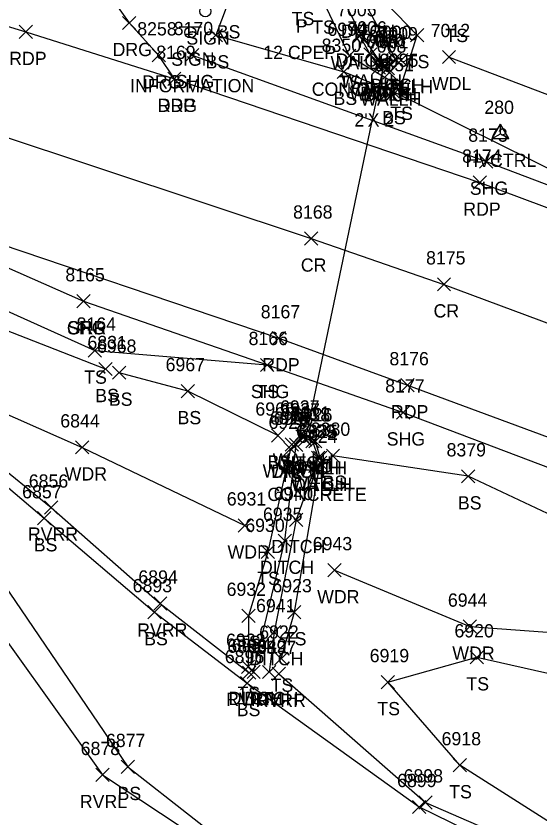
# Model space of a CAD drawing. Extents: x 1588028 to 1589597, y 137576 to 138176.
# Drawn here: x 1589126.2 to 1589205.2, y 137712.9 to 137833.8 of the extents above; entities that cross this region are included whole.
import ezdxf

# ---------------------------------------------------------------- set-up
doc = ezdxf.new("R2010")
doc.units = 0
for name, color, linetype in [('C_A', 7, 'Continuous'), ('C_I', 7, 'Continuous'), ('CPSM', 7, 'Continuous'), ('D_A', 7, 'Continuous'), ('D_C', 7, 'Continuous'), ('D_I', 7, 'Continuous'), ('D_TIC', 7, 'Continuous'), ('DD', 7, 'Continuous'), ('DDEFAULT', 7, 'Continuous'), ('DHW', 7, 'Continuous'), ('L_A', 7, 'Continuous'), ('L_I', 7, 'Continuous'), ('L_TIC', 7, 'Continuous'), ('LAWA', 7, 'Continuous'), ('LAWE', 7, 'Continuous'), ('LELB', 7, 'Continuous'), ('P_A', 7, 'Continuous'), ('P_I', 7, 'Continuous'), ('P_TIC', 7, 'Continuous'), ('PET', 7, 'Continuous'), ('PRC', 7, 'Continuous'), ('PSU', 7, 'Continuous'), ('R_A', 7, 'Continuous'), ('R_I', 7, 'Continuous'), ('R_TIC', 7, 'Continuous'), ('RDG', 7, 'Continuous'), ('RGR', 7, 'Continuous'), ('S_A', 7, 'Continuous'), ('S_C', 7, 'Continuous'), ('SSGN', 7, 'Continuous')]:
    doc.layers.add(name, color=color, linetype=linetype)

msp = doc.modelspace()

# ---------------------------------------------------------------- linework, layer by layer
at = {"layer": 'CPSM'}
for p, q in [((1589198.01, 137815.36), (1589199.26, 137817.52)), ((1589200.51, 137815.36), (1589199.26, 137817.52)), ((1589199.26, 137816.08), (1589199.26, 137817.52)), ((1589198.01, 137815.36), (1589199.26, 137816.08)), ((1589199.26, 137816.08), (1589199.26, 137816.08)), ((1589199.26, 137816.08), (1589200.51, 137815.36)), ((1589198.01, 137815.36), (1589200.51, 137815.36))]:
    msp.add_line(p, q, dxfattribs=at)
at = {"layer": 'D_TIC'}
for points in [[(1589177.02, 137829.81), (1589179.02, 137831.81)], [(1589179.02, 137829.81), (1589177.02, 137831.81)], [(1589177.15, 137830.2), (1589179.15, 137832.2)], [(1589179.15, 137830.2), (1589177.15, 137832.2)], [(1589178.61, 137827.05), (1589180.61, 137829.05)], [(1589180.61, 137827.05), (1589178.61, 137829.05)], [(1589182.37, 137826.39), (1589184.37, 137828.39)], [(1589184.37, 137826.39), (1589182.37, 137828.39)], [(1589183.27, 137826.17), (1589185.27, 137828.17)], [(1589185.27, 137826.17), (1589183.27, 137828.17)], [(1589179.88, 137825.08), (1589181.88, 137827.08)], [(1589181.88, 137825.08), (1589179.88, 137827.08)], [(1589180.26, 137825.74), (1589182.26, 137827.74)], [(1589182.26, 137825.74), (1589180.26, 137827.74)], [(1589180.57, 137825.18), (1589182.57, 137827.18)], [(1589182.57, 137825.18), (1589180.57, 137827.18)], [(1589181.25, 137824.97), (1589183.25, 137826.97)], [(1589183.25, 137824.97), (1589181.25, 137826.97)], [(1589181.5, 137824.32), (1589183.5, 137826.32)], [(1589183.5, 137824.32), (1589181.5, 137826.32)], [(1589168.3, 137769.89), (1589170.3, 137771.89)], [(1589170.3, 137769.89), (1589168.3, 137771.89)], [(1589168.38, 137769.46), (1589170.38, 137771.46)], [(1589170.38, 137769.46), (1589168.38, 137771.46)], [(1589166.78, 137768.23), (1589168.78, 137770.23)], [(1589168.78, 137768.23), (1589166.78, 137770.23)], [(1589167.42, 137768.19), (1589169.42, 137770.19)], [(1589169.42, 137768.19), (1589167.42, 137770.19)], [(1589168.78, 137768.97), (1589170.78, 137770.97)], [(1589170.78, 137768.97), (1589168.78, 137770.97)], [(1589169.9, 137768.71), (1589171.9, 137770.71)], [(1589171.9, 137768.71), (1589169.9, 137770.71)], [(1589170.32, 137768.71), (1589172.32, 137770.71)], [(1589172.32, 137768.71), (1589170.32, 137770.71)], [(1589170.74, 137766.24), (1589172.74, 137768.24)], [(1589172.74, 137766.24), (1589170.74, 137768.24)], [(1589171.05, 137766.21), (1589173.05, 137768.21)], [(1589173.05, 137766.21), (1589171.05, 137768.21)], [(1589167.42, 137756.85), (1589169.42, 137758.85)], [(1589169.42, 137756.85), (1589167.42, 137758.85)], [(1589165.72, 137753.72), (1589167.72, 137755.72)], [(1589167.72, 137753.72), (1589165.72, 137755.72)], [(1589164.11, 137739.94), (1589166.11, 137741.94)], [(1589166.11, 137739.94), (1589164.11, 137741.94)], [(1589161.01, 137733.95), (1589163.01, 137735.95)], [(1589163.01, 137733.95), (1589161.01, 137735.95)], [(1589163.35, 137733.92), (1589165.35, 137735.92)], [(1589165.35, 137733.92), (1589163.35, 137735.92)]]:
    msp.add_lwpolyline(points, dxfattribs=at)
at = {"layer": 'DD'}
for points in [[(1589174.09, 137841.27), (1589178.94, 137835.55), (1589183.37, 137827.39), (1589182.25, 137825.97), (1589181.26, 137826.74), (1589178.15, 137831.2), (1589174.19, 137838.92)], [(1589162.01, 137734.95), (1589166.72, 137754.72), (1589168.42, 137769.19), (1589169.38, 137770.46), (1589170.9, 137769.71), (1589171.74, 137767.24), (1589168.42, 137757.85), (1589165.11, 137740.94), (1589164.35, 137734.92)]]:
    msp.add_lwpolyline(points, dxfattribs=at)
at = {"layer": 'DDEFAULT'}
msp.add_lwpolyline([(1589181.57, 137826.18), (1589169.78, 137769.97)], dxfattribs=at)
at = {"layer": 'DHW'}
for points in [[(1589178.02, 137830.81), (1589179.61, 137828.05), (1589180.88, 137826.08), (1589182.5, 137825.32), (1589184.27, 137827.17)], [(1589172.05, 137767.21), (1589171.32, 137769.71), (1589169.3, 137770.89), (1589167.78, 137769.23)]]:
    msp.add_lwpolyline(points, dxfattribs=at)
at = {"layer": 'L_TIC'}
for points in [[(1589155.32, 137829.93), (1589157.32, 137831.93)], [(1589157.32, 137829.93), (1589155.32, 137831.93)], [(1589185.69, 137829.97), (1589187.69, 137831.97)], [(1589187.69, 137829.97), (1589185.69, 137831.97)], [(1589175.44, 137826.84), (1589177.44, 137828.84)], [(1589177.44, 137826.84), (1589175.44, 137828.84)], [(1589190.48, 137826.66), (1589192.48, 137828.66)], [(1589192.48, 137826.66), (1589190.48, 137828.66)], [(1589174.62, 137824.43), (1589176.62, 137826.43)], [(1589176.62, 137824.43), (1589174.62, 137826.43)], [(1589181.94, 137821.51), (1589183.94, 137823.51)], [(1589183.94, 137821.51), (1589181.94, 137823.51)], [(1589183.21, 137822.17), (1589185.21, 137824.17)], [(1589185.21, 137822.17), (1589183.21, 137824.17)], [(1589137.04, 137782.39), (1589139.04, 137784.39)], [(1589139.04, 137782.39), (1589137.04, 137784.39)], [(1589163.04, 137780.22), (1589165.04, 137782.22)], [(1589165.04, 137780.22), (1589163.04, 137782.22)], [(1589138.68, 137779.61), (1589140.68, 137781.61)], [(1589140.68, 137779.61), (1589138.68, 137781.61)], [(1589140.73, 137779.06), (1589142.73, 137781.06)], [(1589142.73, 137779.06), (1589140.73, 137781.06)], [(1589151.09, 137776.28), (1589153.09, 137778.28)], [(1589153.09, 137776.28), (1589151.09, 137778.28)], [(1589164.68, 137769.58), (1589166.68, 137771.58)], [(1589166.68, 137769.58), (1589164.68, 137771.58)], [(1589135.15, 137767.8), (1589137.15, 137769.8)], [(1589137.15, 137767.8), (1589135.15, 137769.8)], [(1589166.56, 137767.59), (1589168.56, 137769.59)], [(1589168.56, 137767.59), (1589166.56, 137769.59)], [(1589171.03, 137765.48), (1589173.03, 137767.48)], [(1589173.03, 137765.48), (1589171.03, 137767.48)], [(1589172.98, 137766.54), (1589174.98, 137768.54)], [(1589174.98, 137766.54), (1589172.98, 137768.54)], [(1589193.38, 137763.43), (1589195.38, 137765.43)], [(1589195.38, 137763.43), (1589193.38, 137765.43)], [(1589130.45, 137758.72), (1589132.45, 137760.72)], [(1589132.45, 137758.72), (1589130.45, 137760.72)], [(1589129.4, 137757.11), (1589131.4, 137759.11)], [(1589131.4, 137757.11), (1589129.4, 137759.11)], [(1589159.7, 137756.03), (1589161.7, 137758.03)], [(1589161.7, 137756.03), (1589159.7, 137758.03)], [(1589163.14, 137752.05), (1589165.14, 137754.05)], [(1589165.14, 137752.05), (1589163.14, 137754.05)], [(1589173.22, 137749.28), (1589175.22, 137751.28)], [(1589175.22, 137749.28), (1589173.22, 137751.28)], [(1589146.93, 137744.25), (1589148.93, 137746.25)], [(1589148.93, 137744.25), (1589146.93, 137746.25)], [(1589146.06, 137742.95), (1589148.06, 137744.95)], [(1589148.06, 137742.95), (1589146.06, 137744.95)], [(1589167.15, 137742.94), (1589169.15, 137744.94)], [(1589169.15, 137742.94), (1589167.15, 137744.94)], [(1589160.24, 137742.4), (1589162.24, 137744.4)], [(1589162.24, 137742.4), (1589160.24, 137744.4)], [(1589193.61, 137740.77), (1589195.61, 137742.77)], [(1589195.61, 137740.77), (1589193.61, 137742.77)], [(1589165.16, 137735.94), (1589167.16, 137737.94)], [(1589167.16, 137735.94), (1589165.16, 137737.94)], [(1589194.69, 137736.14), (1589196.69, 137738.14)], [(1589196.69, 137736.14), (1589194.69, 137738.14)], [(1589160.16, 137734.71), (1589162.16, 137736.71)], [(1589162.16, 137734.71), (1589160.16, 137736.71)], [(1589160.35, 137733.82), (1589162.35, 137735.82)], [(1589162.35, 137733.82), (1589160.35, 137735.82)], [(1589164.8, 137733.64), (1589166.8, 137735.64)], [(1589166.8, 137733.64), (1589164.8, 137735.64)], [(1589160.02, 137732.26), (1589162.02, 137734.26)], [(1589162.02, 137732.26), (1589160.02, 137734.26)], [(1589181.26, 137732.4), (1589183.26, 137734.4)], [(1589183.26, 137732.4), (1589181.26, 137734.4)], [(1589142.04, 137719.61), (1589144.04, 137721.61)], [(1589144.04, 137719.61), (1589142.04, 137721.61)], [(1589192.1, 137719.87), (1589194.1, 137721.87)], [(1589194.1, 137719.87), (1589192.1, 137721.87)], [(1589138.23, 137718.4), (1589140.23, 137720.4)], [(1589140.23, 137718.4), (1589138.23, 137720.4)], [(1589185.97, 137713.57), (1589187.97, 137715.57)], [(1589187.97, 137713.57), (1589185.97, 137715.57)], [(1589186.94, 137714.26), (1589188.94, 137716.26)], [(1589188.94, 137714.26), (1589186.94, 137716.26)]]:
    msp.add_lwpolyline(points, dxfattribs=at)
at = {"layer": 'LAWA'}
for points in [[(1589191.48, 137827.66), (1589208.47, 137821.19), (1589231.01, 137810.22), (1589260.79, 137799.99), (1589288.54, 137790.36), (1589312.49, 137778.55), (1589337.68, 137767.31), (1589356.85, 137760.89), (1589388.23, 137746.7), (1589420.91, 137733.88), (1589453.12, 137717.84), (1589474.94, 137709.38)], [(1588990.27, 137820.39), (1589015.31, 137815.18), (1589044.24, 137809.21), (1589082.76, 137797.73), (1589102.27, 137783.77), (1589136.15, 137768.8), (1589160.7, 137757.03)], [(1589174.22, 137750.28), (1589194.61, 137741.77), (1589225.59, 137739.5), (1589259.02, 137733.29), (1589293.77, 137713.14), (1589318.53, 137702.11), (1589332.78, 137696.04)]]:
    msp.add_lwpolyline(points, dxfattribs=at)
at = {"layer": 'LAWE'}
for points in [[(1588965.44, 137832.87), (1588973.43, 137818.62), (1588989.6, 137813.18), (1589022.84, 137804.12), (1589064.64, 137785.89), (1589085.42, 137779.69), (1589097.72, 137781.17), (1589112.63, 137775.03), (1589131.45, 137759.72), (1589147.93, 137745.25), (1589161.35, 137734.82)], [(1588998.37, 137781.01), (1589022.99, 137780.11), (1589053.11, 137769.29), (1589085.17, 137761.52), (1589118.32, 137748.59), (1589139.23, 137719.4), (1589162.49, 137704.02), (1589194.14, 137678.84), (1589218.55, 137662.87), (1589237.06, 137655.88), (1589274.24, 137640.2), (1589299.98, 137630.61), (1589325.3, 137627.35), (1589364.55, 137614.89), (1589400.15, 137603.63), (1589430.64, 137600.05), (1589464.28, 137596.09), (1589486.71, 137581.4)], [(1589165.8, 137734.64), (1589187.94, 137715.26), (1589212.73, 137704.5), (1589228.51, 137693.02), (1589244.33, 137677.06), (1589269.62, 137665.25), (1589295.65, 137657.92), (1589324.97, 137652.81), (1589365.32, 137641.86), (1589399.41, 137634.7), (1589423.88, 137632.18), (1589457.23, 137620.82), (1589479.74, 137612.88)]]:
    msp.add_lwpolyline(points, dxfattribs=at)
at = {"layer": 'LELB'}
for points in [[(1589172.43, 137836.17), (1589176.44, 137827.84), (1589184.21, 137823.17), (1589186.69, 137830.97), (1589175.8, 137842.19)], [(1589158, 137835.46), (1589156.32, 137830.93), (1589175.62, 137825.43), (1589182.94, 137822.51), (1589209.46, 137809.41), (1589234.23, 137800.33), (1589267.46, 137786.74), (1589294.29, 137776.74), (1589322.35, 137767.05), (1589346.37, 137758.08), (1589352.86, 137754.06), (1589353.51, 137751.68), (1589354.61, 137751.57), (1589355.75, 137752.57)], [(1588982.15, 137832.74), (1589014.45, 137822.9), (1589047.33, 137817.07), (1589086.55, 137806.43), (1589114.04, 137794.2), (1589138.04, 137783.39), (1589164.04, 137781.22)], [(1588992.37, 137810.47), (1589023.33, 137801.66), (1589065.26, 137783.21), (1589085.4, 137777.87), (1589097.27, 137780.08), (1589112.23, 137773.55), (1589130.4, 137758.11), (1589147.06, 137743.95), (1589161.02, 137733.26), (1589186.97, 137714.57), (1589213.06, 137701.82), (1589227.47, 137691.94), (1589245.18, 137673.31), (1589268.48, 137660.8), (1589296.93, 137655.07), (1589325.66, 137650.73)], [(1589139.68, 137780.61), (1589111.56, 137791.56), (1589090.72, 137796.64)], [(1588992.54, 137792.39), (1589023.3, 137782.03), (1589052.1, 137771.44), (1589084.42, 137763.28), (1589121.54, 137752.14), (1589143.04, 137720.61), (1589163.05, 137704.95), (1589194.58, 137680.14), (1589220, 137665.12), (1589237.76, 137657.31), (1589273.63, 137642.37), (1589300.04, 137631.76), (1589324.52, 137628.67), (1589366.23, 137617.74), (1589400.05, 137606.05), (1589430.12, 137603.56), (1589464.26, 137598.64), (1589483.45, 137589.04)], [(1589165.68, 137770.58), (1589152.09, 137777.28), (1589141.73, 137780.06)], [(1589167.56, 137768.59), (1589164.14, 137753.05), (1589161.24, 137743.4), (1589161.16, 137735.71)], [(1589346.98, 137708.09), (1589339.5, 137707.7), (1589337.39, 137703.26), (1589330.57, 137699.32), (1589318.71, 137707.48), (1589314.78, 137719.03), (1589294.5, 137728.6), (1589257.75, 137742.55), (1589219.17, 137752.77), (1589194.38, 137764.43), (1589173.98, 137767.54)], [(1589166.16, 137736.94), (1589168.15, 137743.94), (1589172.03, 137766.48)], [(1589211.6, 137709.12), (1589193.1, 137720.87), (1589182.26, 137733.4), (1589195.69, 137737.14), (1589211.53, 137733.59)]]:
    msp.add_lwpolyline(points, dxfattribs=at)
at = {"layer": 'P_TIC'}
for points in [[(1589126.64, 137830.45), (1589128.64, 137832.45)], [(1589128.64, 137830.45), (1589126.64, 137832.45)], [(1589151.74, 137826.96), (1589153.74, 137828.96)], [(1589153.74, 137826.96), (1589151.74, 137828.96)], [(1589149.05, 137823.37), (1589151.05, 137825.37)], [(1589151.05, 137823.37), (1589149.05, 137825.37)], [(1589196.07, 137810.88), (1589198.07, 137812.88)], [(1589198.07, 137810.88), (1589196.07, 137812.88)], [(1589195.14, 137807.72), (1589197.14, 137809.72)], [(1589197.14, 137807.72), (1589195.14, 137809.72)], [(1589169.7, 137799.29), (1589171.7, 137801.29)], [(1589171.7, 137799.29), (1589169.7, 137801.29)], [(1589189.72, 137792.38), (1589191.72, 137794.38)], [(1589191.72, 137792.38), (1589189.72, 137794.38)], [(1589135.35, 137789.83), (1589137.35, 137791.83)], [(1589137.35, 137789.83), (1589135.35, 137791.83)], [(1589164.82, 137784.25), (1589166.82, 137786.25)], [(1589166.82, 137784.25), (1589164.82, 137786.25)], [(1589163.04, 137780.22), (1589165.04, 137782.22)], [(1589165.04, 137780.22), (1589163.04, 137782.22)], [(1589184.23, 137777.17), (1589186.23, 137779.17)], [(1589186.23, 137777.17), (1589184.23, 137779.17)], [(1589183.55, 137773.07), (1589185.55, 137775.07)], [(1589185.55, 137773.07), (1589183.55, 137775.07)]]:
    msp.add_lwpolyline(points, dxfattribs=at)
at = {"layer": 'PET'}
for points in [[(1588976.42, 137837.98), (1588964.71, 137855.4), (1588953.74, 137871.46), (1588980.82, 137866.91), (1589021.21, 137859.55), (1589054.58, 137852.92), (1589087.36, 137843.77), (1589127.64, 137831.45), (1589150.05, 137824.37), (1589196.14, 137808.72), (1589243.87, 137790.96), (1589276.87, 137778.08), (1589322.25, 137759.62), (1589367.82, 137740.82), (1589401.87, 137726.11), (1589432.81, 137712.85), (1589459.76, 137701.46)], [(1588976.42, 137837.98), (1589015.38, 137829.77), (1589047.77, 137821.87), (1589087.62, 137811.07), (1589117.34, 137801.67), (1589165.82, 137785.25), (1589185.23, 137778.17), (1589232.28, 137760.8), (1589265.32, 137747.81), (1589310.31, 137729.83), (1589359.63, 137709.23), (1589389.55, 137696.8), (1589422.31, 137682.69), (1589446.91, 137672.54)]]:
    msp.add_lwpolyline(points, dxfattribs=at)
at = {"layer": 'PRC'}
msp.add_lwpolyline([(1588964.71, 137855.4), (1588980.14, 137852.51), (1589018.19, 137844.35), (1589051.57, 137836.27), (1589092.27, 137825.07), (1589122.68, 137816.23), (1589170.7, 137800.29), (1589190.72, 137793.38), (1589238.44, 137775.62), (1589271.31, 137762.4), (1589315.94, 137744.35), (1589366.22, 137723.58), (1589395.71, 137710.87), (1589428.18, 137697.42), (1589453.33, 137686.42)], dxfattribs=at)
at = {"layer": 'PSU'}
for points in [[(1589152.74, 137827.96), (1589197.07, 137811.88), (1589244.81, 137793.79), (1589277.33, 137781.11), (1589323.36, 137762.65), (1589353.23, 137749.52), (1589368.68, 137743.62), (1589402.84, 137728.77), (1589433.2, 137714.7), (1589460.72, 137703.44)], [(1589136.35, 137790.83), (1589164.04, 137781.22), (1589184.55, 137774.07), (1589230.78, 137756.58), (1589263.84, 137744.47), (1589309.17, 137726.92), (1589358.43, 137707.04), (1589387.87, 137693.92), (1589420.52, 137679.79), (1589445.83, 137669.38)]]:
    msp.add_lwpolyline(points, dxfattribs=at)
at = {"layer": 'R_TIC'}
for points in [[(1589142.24, 137831.79), (1589144.24, 137833.79)], [(1589144.24, 137831.79), (1589142.24, 137833.79)], [(1589146.71, 137826.91), (1589148.71, 137828.91)], [(1589148.71, 137826.91), (1589146.71, 137828.91)], [(1589146.71, 137826.91), (1589148.71, 137828.91)], [(1589148.71, 137826.91), (1589146.71, 137828.91)], [(1589149.05, 137823.37), (1589151.05, 137825.37)], [(1589151.05, 137823.37), (1589149.05, 137825.37)], [(1589135.35, 137789.83), (1589137.35, 137791.83)], [(1589137.35, 137789.83), (1589135.35, 137791.83)]]:
    msp.add_lwpolyline(points, dxfattribs=at)
at = {"layer": 'RDG'}
for points in [[(1589030.3, 137954.92), (1589069.21, 137915.71), (1589093.48, 137893.77), (1589119.98, 137869.52), (1589132.81, 137847.36), (1589143.24, 137832.79), (1589147.71, 137827.91)], [(1589150.05, 137824.37), (1589147.71, 137827.91)]]:
    msp.add_lwpolyline(points, dxfattribs=at)
at = {"layer": 'RGR'}
msp.add_lwpolyline([(1588981.28, 137836.13), (1589015.23, 137828.95), (1589047.72, 137821.35), (1589087.45, 137810.42), (1589116.48, 137799.61), (1589136.35, 137790.83)], dxfattribs=at)
at = {"layer": 'SSGN'}
for p, q in [((1589150.8, 137832.19), (1589154.13, 137832.19)), ((1589152.45, 137831.36), (1589152.45, 137831.36))]:
    msp.add_line(p, q, dxfattribs=at)
for centre in [(1589154.73, 137834.55), (1589152.45, 137831.36)]:
    msp.add_circle(centre, 0.833, dxfattribs=at)

# ---------------------------------------------------------------- texts
at = {"layer": 'C_A'}
msp.add_text('HVCTRL', height=2, dxfattribs=at).set_placement((1589193.96, 137811.08))
at = {"layer": 'C_I'}
msp.add_text('280', height=2, dxfattribs=at).set_placement((1589196.81, 137819.08))
at = {"layer": 'D_A'}
for s, p in [('P', (1589168.37, 137831.35)), ('DITCH', (1589175.17, 137830.55)), ('DITCH', (1589174.39, 137826.2)), ('WALLH', (1589173.61, 137825.81)), ('WALLH', (1589175.2, 137823.05)), ('DITCH', (1589179.6, 137822.39)), ('DITCH', (1589177.5, 137821.74)), ('BOXC', (1589178.07, 137821.18)), ('WALLH', (1589179.86, 137822.17)), ('WALLH', (1589176.47, 137821.08)), ('WALLH', (1589178.09, 137820.32)), ('DITCH', (1589178.48, 137820.97)), ('WALLH', (1589164.89, 137765.89)), ('DITCH', (1589165.61, 137765.46)), ('BOXC', (1589166.28, 137764.97)), ('WALLH', (1589166.91, 137764.71)), ('DITCH', (1589167.14, 137764.71)), ('WALLH', (1589163.37, 137764.23)), ('DITCH', (1589164.66, 137764.19)), ('WALLH', (1589167.64, 137762.21)), ('DITCH', (1589167.97, 137762.24)), ('DITCH', (1589164.66, 137752.85)), ('DITCH', (1589162.96, 137749.72)), ('DITCH', (1589161.35, 137735.94)), ('DITCH', (1589158.24, 137729.95)), ('DITCH', (1589160.59, 137729.92))]:
    msp.add_text(s, height=2, dxfattribs=at).set_placement(p)
at = {"layer": 'D_C'}
for s, p in [('12 CPEP', (1589163.46, 137827.35)), ('CONCRETE', (1589170.77, 137821.81)), ("2'X 2'", (1589177.21, 137817.18)), ('CONCRETE', (1589164.07, 137760.71))]:
    msp.add_text(s, height=2, dxfattribs=at).set_placement(p)
at = {"layer": 'D_I'}
for s, p in [('7005', (1589174.6, 137833.81)), ('7006', (1589176.14, 137831.05)), ('7002', (1589177.85, 137829.74)), ('7000', (1589179.86, 137830.39)), ('7009', (1589180.84, 137830.17)), ('7007', (1589177.47, 137829.08)), ('7010', (1589178.71, 137829.18)), ('7001', (1589179.4, 137828.97)), ('7008', (1589179.09, 137828.32)), ('6927', (1589165.99, 137773.89)), ('6937', (1589166.07, 137773.46)), ('7011', (1589167.58, 137772.97)), ('6938', (1589167.6, 137772.71)), ('6926', (1589167.95, 137772.71)), ('6928', (1589164.47, 137772.23)), ('6936', (1589165.06, 137772.19)), ('6939', (1589168.42, 137770.24)), ('6925', (1589168.75, 137770.21)), ('6940', (1589165.03, 137760.85)), ('6935', (1589163.42, 137757.72)), ('6941', (1589162.37, 137743.94)), ('6934', (1589158.7, 137737.95)), ('6942', (1589161.05, 137737.92))]:
    msp.add_text(s, height=2, dxfattribs=at).set_placement(p)
at = {"layer": 'L_A'}
for s, p in [('TS', (1589167.75, 137832.46)), ('TS', (1589170.84, 137831.17)), ('BS', (1589156.44, 137830.46)), ('TS', (1589190.94, 137829.91)), ('BS', (1589154.76, 137825.93)), ('TS', (1589185.1, 137825.97)), ('TS', (1589174.85, 137822.84)), ('WDL', (1589188.9, 137822.66)), ('BS', (1589174.06, 137820.43)), ('BS', (1589181.39, 137817.51)), ('TS', (1589182.62, 137818.17)), ('TS', (1589136.45, 137778.39)), ('BS', (1589138.12, 137775.61)), ('TS', (1589162.45, 137776.22)), ('BS', (1589140.17, 137775.06)), ('BS', (1589150.53, 137772.28)), ('BS', (1589164.12, 137765.58)), ('WDR', (1589133.51, 137763.8)), ('TS', (1589165.97, 137763.59)), ('BS', (1589172.42, 137762.54)), ('TS', (1589170.44, 137761.48)), ('BS', (1589192.82, 137759.43)), ('RVRR', (1589127.96, 137754.72)), ('BS', (1589128.84, 137753.11)), ('WDR', (1589158.07, 137752.03)), ('TS', (1589162.55, 137748.05)), ('WDR', (1589171.59, 137745.28)), ('RVRR', (1589144.44, 137740.25)), ('BS', (1589145.5, 137738.95)), ('TS', (1589166.56, 137738.94)), ('TS', (1589159.65, 137738.4)), ('WDR', (1589191.98, 137736.77)), ('TS', (1589164.57, 137731.94)), ('TS', (1589194.1, 137732.14)), ('TS', (1589159.57, 137730.71)), ('RVRR', (1589157.86, 137729.82)), ('RVRR', (1589162.31, 137729.64)), ('BS', (1589159.46, 137728.26)), ('TS', (1589180.67, 137728.4)), ('TS', (1589191.51, 137715.87)), ('BS', (1589141.48, 137715.61)), ('RVRL', (1589135.79, 137714.4))]:
    msp.add_text(s, height=2, dxfattribs=at).set_placement(p)
at = {"layer": 'L_I'}
for s, p in [('6994', (1589173.14, 137830.84)), ('7012', (1589188.71, 137830.66)), ('8350', (1589172.27, 137828.43)), ('6995', (1589180.91, 137826.17)), ('8351', (1589180.25, 137825.51)), ('8164', (1589135.3, 137786.39)), ('6831', (1589136.94, 137783.61)), ('8166', (1589161.25, 137784.22)), ('6968', (1589138.38, 137783.06)), ('6967', (1589148.73, 137780.28)), ('6966', (1589162.27, 137773.58)), ('6844', (1589132.84, 137771.8)), ('6929', (1589164.25, 137771.59)), ('8380', (1589170.63, 137770.54)), ('6924', (1589168.72, 137769.48)), ('8379', (1589191.11, 137767.43)), ('6856', (1589128.09, 137762.72)), ('6857', (1589127.09, 137761.11)), ('6931', (1589157.96, 137760.03)), ('6930', (1589160.75, 137756.05)), ('6943', (1589170.92, 137753.28)), ('6894', (1589144.62, 137748.25)), ('6893', (1589143.76, 137746.95)), ('6932', (1589157.93, 137746.4)), ('6923', (1589164.84, 137746.94)), ('6944', (1589191.31, 137744.77)), ('6920', (1589192.3, 137740.14)), ('6922', (1589162.85, 137739.94)), ('6933', (1589157.85, 137738.71)), ('6895', (1589158.04, 137737.82)), ('6897', (1589162.49, 137737.64)), ('6896', (1589157.66, 137736.26)), ('6919', (1589179.52, 137736.4)), ('6877', (1589139.73, 137723.61)), ('6918', (1589190.36, 137723.87)), ('6878', (1589135.92, 137722.4)), ('6899', (1589183.65, 137717.57)), ('6898', (1589184.63, 137718.26))]:
    msp.add_text(s, height=2, dxfattribs=at).set_placement(p)
at = {"layer": 'P_A'}
for s, p in [('RDP', (1589125.13, 137826.45)), ('SHG', (1589150.27, 137822.96)), ('RDP', (1589147.54, 137819.37)), ('SHG', (1589194.61, 137806.88)), ('RDP', (1589193.63, 137803.72)), ('CR', (1589169.13, 137795.29)), ('CR', (1589189.15, 137788.38)), ('SHG', (1589133.89, 137785.83)), ('RDP', (1589163.31, 137780.25)), ('SHG', (1589161.58, 137776.22)), ('RDP', (1589182.72, 137773.17)), ('SHG', (1589182.08, 137769.07))]:
    msp.add_text(s, height=2, dxfattribs=at).set_placement(p)
at = {"layer": 'P_I'}
for s, p in [('8170', (1589149.96, 137830.96)), ('8169', (1589147.31, 137827.37)), ('8173', (1589194.38, 137814.88)), ('8174', (1589193.45, 137811.72)), ('8168', (1589167.96, 137803.29)), ('8175', (1589188.02, 137796.38)), ('8165', (1589133.61, 137793.83)), ('8167', (1589163.08, 137788.25)), ('8166', (1589161.25, 137784.22)), ('8176', (1589182.49, 137781.17)), ('8177', (1589181.85, 137777.07))]:
    msp.add_text(s, height=2, dxfattribs=at).set_placement(p)
at = {"layer": 'R_A'}
for s, p in [('DRG', (1589140.73, 137827.79)), ('DRG', (1589145.2, 137822.91)), ('DRG', (1589145.2, 137822.91)), ('DRG', (1589147.54, 137819.37)), ('GRR', (1589133.84, 137785.83))]:
    msp.add_text(s, height=2, dxfattribs=at).set_placement(p)
at = {"layer": 'R_I'}
for s, p in [('8258', (1589144.45, 137830.91)), ('8258', (1589144.45, 137830.91)), ('8169', (1589147.31, 137827.37)), ('8165', (1589133.61, 137793.83))]:
    msp.add_text(s, height=2, dxfattribs=at).set_placement(p)
at = {"layer": 'S_A'}
for p in [(1589151.87, 137829.53), (1589149.58, 137826.34)]:
    msp.add_text('SIGN', height=2, dxfattribs=at).set_placement(p)
at = {"layer": 'S_C'}
msp.add_text('INFORMATION', height=2, dxfattribs=at).set_placement((1589143.38, 137822.34))

doc.saveas('drawing.dxf')
